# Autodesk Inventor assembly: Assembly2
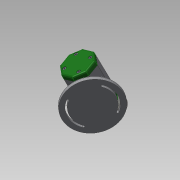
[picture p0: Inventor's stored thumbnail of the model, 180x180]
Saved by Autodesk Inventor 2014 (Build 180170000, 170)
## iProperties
Created: 2017-06
Part Number: Assembly2
Document SubType Name: Assembly
Designer: user
Author: user
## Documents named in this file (14)
- C:\Users\user\Desktop\470608V1003\Assembly2.iam
- C:\Users\user\Desktop\470608V1003\본체.ipt
- C:\Users\user\Desktop\470608V1003\와셔 8x17.ipt
- C:\Users\user\Desktop\470608V1003\축.ipt
- C:\Users\user\Desktop\470608V1003\V벨트풀리.ipt
- C:\Users\user\Desktop\470608V1003\고무캡.ipt
- C:\Users\user\Desktop\470608V1003\너트 M 8.ipt
- C:\Users\user\Desktop\470608V1003\뒤커버.ipt
- C:\Users\user\Desktop\470608V1003\베어링 15 x 32 x 9.ipt
- C:\Users\user\Desktop\470608V1003\볼트 M4 x 12.ipt
- C:\Users\user\Desktop\470608V1003\스프링와셔 8.ipt
- C:\Users\user\Desktop\470608V1003\앞커버.ipt
- C:\Users\user\Desktop\470608V1003\오일 실 15 25 7.ipt
- C:\Users\user\Desktop\470608V1003\키 3 x 3 x 12.ipt
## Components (2 placed, 2 different names)
1. V벨트풀리:1 — Mate:17, Mate:18, Mate:19, Mate:21
2. 고무캡:1 — Mate:30, Mate:31
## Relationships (6: Mate 6)
- Mate:17: V벨트풀리:1
- Mate:18: V벨트풀리:1
- Mate:19: V벨트풀리:1
- Mate:21: V벨트풀리:1
- Mate:30: 고무캡:1
- Mate:31: 고무캡:1
